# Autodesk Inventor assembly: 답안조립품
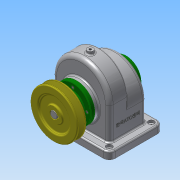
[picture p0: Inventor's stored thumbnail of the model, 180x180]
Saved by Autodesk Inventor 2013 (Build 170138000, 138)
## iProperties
Created: 2017-11
Part Number: 답안조립품
Document SubType Name: Assembly
Designer: Administrator
Author: Administrator
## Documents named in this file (14)
- C:\Users\Administrator\Desktop\471108V1016\답안조립품.iam
- C:\Users\Administrator\Desktop\471108V1016\본체.ipt
- C:\Users\Administrator\Desktop\471108V1016\V-벨트풀리.ipt
- C:\Users\Administrator\Desktop\471108V1016\뒤커버.ipt
- C:\Users\Administrator\Desktop\471108V1016\멈춤나사 - M4 x 10.ipt
- 멈춤나사 - M4 x 10.ipt
- C:\Users\Administrator\Desktop\471108V1016\베어링 6002.ipt
- C:\Users\Administrator\Desktop\471108V1016\볼트 M3 x 8.ipt
- C:\Users\Administrator\Desktop\471108V1016\스퍼기어.ipt
- C:\Users\Administrator\Desktop\471108V1016\앞커버.ipt
- C:\Users\Administrator\Desktop\471108V1016\오일 실 15 30 7.ipt
- C:\Users\Administrator\Desktop\471108V1016\축.ipt
- C:\Users\Administrator\Desktop\471108V1016\키 - 5 x 5 x 18.ipt
- C:\Users\Administrator\Desktop\471108V1016\키 - 6 x 6 x 22.ipt
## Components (1 placed, 1 different names)
1. V-벨트풀리:1 — 플러쉬:1
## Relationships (1: Flush 1)
- 플러쉬:1 [Flush]: V-벨트풀리:1
